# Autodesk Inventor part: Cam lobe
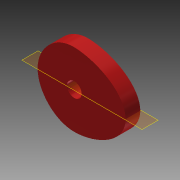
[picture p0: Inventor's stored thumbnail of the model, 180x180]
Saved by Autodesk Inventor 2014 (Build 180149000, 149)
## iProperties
Created: 2008-06
Part Number: Cam lobe
Document SubType Name: Modeling
Designer: tangg
Density: 7.75 g/cm^3
Mass: 5.71787 g
Surface Area: 26.2129 cm^2
Volume: 5.71787 cm^3
Stock Number: Cam lobe
Material: Stainless Steel, 440C
Appearance: Light Red
Author: tangg
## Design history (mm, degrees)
sketch "Sketch1"
  geometry: L1 (-0.008, 11.43)-(-0.008, -11.43); L2 (-0.008, 0.008)-(15.875, -15.875); L3 (0, 0)-(13.517, 13.517); L4 (-0.008, 0.008)-(-14.375, 14.375); L5 (0, 0)-(-13.139, -13.139); L6 (22.225, 3.829)-(22.225, -3.829); L7 (4.981, -15.875)-(-4.981, -15.875); C1 r 3.175 at (0, 0); A1 r 10.081 centre (12.144, 0) between (21.789, -2.931) and (21.789, 2.931); A2 r 19.362 centre (0, 3.487) between (-3.903, -15.478) and (3.903, -15.478); 8 further points
  constraints: 14 end point, 5 midpoint, 3 centre point, 3 point on line, 3 vertical, 2 horizontal, 2 point on circle, 1 coincident, 12 other
  dimensions: "d0" = 6.35 diameter of C1; "d7" = 45 deg angle of L1 L2; "d8" = 45 deg angle of L1 L3; "d9" = 45 deg angle of L5 L1; "d10" = 45 deg angle of L4 L1
extrude "Extrusion1" new body sketch "Sketch1" distance "d1" = 6.35; taper "d2" = 0 deg
sketch "Sketch4"
  geometry: 1 further point
sketch "Sketch5"
  geometry: 1 further point
body "Solid1"
